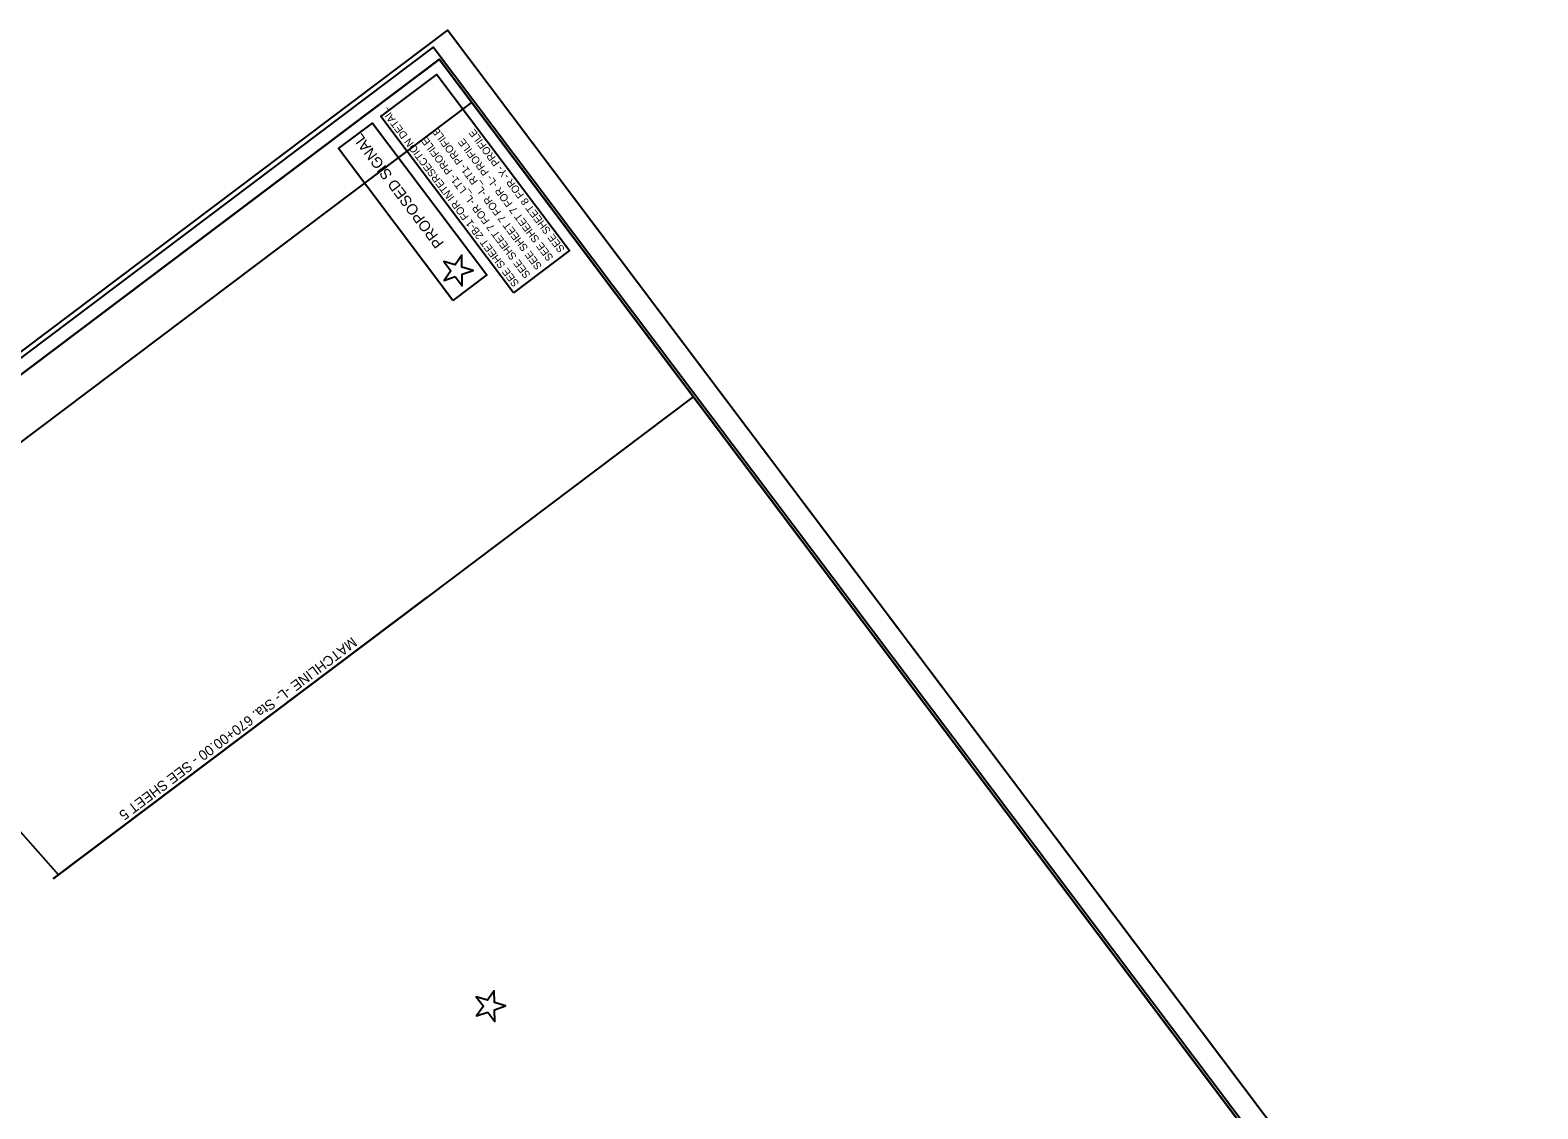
# Model space of a CAD drawing. Extents: x 1262749 to 1264921, y 774795 to 776798.
# Drawn here: x 1263520 to 1264921, y 775796 to 776798 of the extents above; entities that cross this region are included whole.
import ezdxf

# ---------------------------------------------------------------- set-up
doc = ezdxf.new("R2010")
doc.units = 0
for name, color, linetype in [('Matchline', 7, 'Continuous'), ('Prop DSN Text', 7, 'Continuous'), ('Prop Grid Mask', 7, 'Continuous'), ('Prop PHM Label Text', 7, 'Continuous'), ('Prop RDY Traffic Signal CELL', 7, 'Continuous'), ('Sheet Clip Boundary CELL', 7, 'Continuous'), ('Sheet Cutting Line CELL', 7, 'Continuous'), ('Sheet Layout Plan Border', 7, 'Continuous'), ('Sheet Plan CELL', 7, 'Continuous'), ('Sheet Plan Layout CELL', 7, 'Continuous'), ('Sheet Plot Border Inside CELL', 7, 'Continuous'), ('Sheet Plot Border Outside CELL', 7, 'Continuous')]:
    doc.layers.add(name, color=color, linetype=linetype)

msp = doc.modelspace()

# ---------------------------------------------------------------- linework, layer by layer
at = {"layer": 'Matchline'}
msp.add_line((1263542, 776010.3), (1263888.7, 776271.4), dxfattribs=at)
at = {"layer": 'Prop Grid Mask'}
msp.add_lwpolyline([(1263913, 776547.2), (1263806.8, 776688.2), (1263838.2, 776711.9), (1263944.4, 776570.8)], close=True, dxfattribs=at)
at = {"layer": 'Prop PHM Label Text'}
msp.add_lwpolyline([(1263969.4, 776554.3), (1263846.2, 776717.9), (1263898.2, 776757), (1264021.4, 776593.5)], close=True, dxfattribs=at)
at = {"layer": 'Prop RDY Traffic Signal CELL'}
for points in [[(1263915.2, 776569.3), (1263921.7, 776560.6), (1263921.6, 776571.5), (1263931.9, 776575), (1263921.4, 776578.2), (1263921.2, 776589.1), (1263915, 776580.2), (1263904.6, 776583.3), (1263911.1, 776574.7), (1263904.9, 776565.7), (1263915.2, 776569.3)], [(1263945.3, 775886.3), (1263951.9, 775877.6), (1263951.7, 775888.5), (1263962, 775892), (1263951.6, 775895.2), (1263951.4, 775906.1), (1263945.1, 775897.2), (1263934.7, 775900.4), (1263941.3, 775891.7), (1263935, 775882.7), (1263945.3, 775886.3)]]:
    msp.add_lwpolyline(points, dxfattribs=at)
at = {"layer": 'Sheet Clip Boundary CELL'}
msp.add_lwpolyline([(1264772.6, 775612.8), (1264136.1, 776457.8), (1263888.7, 776271.4), (1263888.7, 776271.4), (1263542, 776010.3), (1263546.7, 776013.8), (1263492.1, 776075), (1263297.4, 775826.1), (1263933.9, 774981.1)], close=True, dxfattribs=at)
at = {"layer": 'Sheet Cutting Line CELL'}
msp.add_line((1264920.8, 775453.5), (1263907.9, 776798.2), dxfattribs=at)
at = {"layer": 'Sheet Layout Plan Border'}
msp.add_lwpolyline([(1264772.6, 775612.8), (1263930.3, 776731.1), (1263260.5, 776226.6), (1263374.4, 776075.5), (1263205.4, 775948.2), (1263933.9, 774981.1)], close=True, dxfattribs=at)
at = {"layer": 'Sheet Plan CELL'}
msp.add_lwpolyline([(1263061.5, 776139.4), (1263964, 774941.2), (1264802.7, 775572.9), (1263900.2, 776771.1)], close=True, dxfattribs=at)
at = {"layer": 'Sheet Plan Layout CELL'}
msp.add_lwpolyline([(1263964, 774941.2), (1264802.7, 775572.9), (1263900.2, 776771), (1263230.4, 776266.6), (1263374.4, 776075.5), (1263205.4, 775948.2)], close=True, dxfattribs=at)
at = {"layer": 'Sheet Plot Border Inside CELL'}
msp.add_lwpolyline([(1264897, 775451.8), (1263894.7, 776782.5), (1263052, 776147.8), (1264054.3, 774817.1)], close=True, dxfattribs=at)
at = {"layer": 'Sheet Plot Border Outside CELL'}
msp.add_lwpolyline([(1264920.8, 775453.5), (1263907.9, 776798.2), (1263033.3, 776139.4), (1264046.2, 774794.7)], close=True, dxfattribs=at)

# ---------------------------------------------------------------- texts
at = {"layer": 'Matchline'}
msp.add_text('MATCHLINE -L- Sta. 670+00.00 - SEE SHEET 5', height=9.375, rotation=216.9874, dxfattribs=at).set_placement((1263819.3, 776235))
at = {"layer": 'Prop DSN Text'}
msp.add_text('PROPOSED SIGNAL', height=10, rotation=126.9874, dxfattribs=at).set_placement((1263905.1, 776600.4))
at = {"layer": 'Prop PHM Label Text'}
for s, p in [('SEE SHEET 2B-1 FOR INTERSECTION DETAIL', (1263974.9, 776563.1)), ('SEE SHEET 7 FOR -L_RT1- PROFILE', (1263996.1, 776579)), ('SEE SHEET 8 FOR -Y- PROFILE', (1264017.3, 776594.9)), ('SEE SHEET 7 FOR -L_LT1- PROFILE', (1263985.5, 776571)), ('SEE SHEET 7 FOR -L- PROFILE', (1264006.7, 776587))]:
    msp.add_text(s, height=7, rotation=126.9874, dxfattribs=at).set_placement(p)

doc.saveas('drawing.dxf')
